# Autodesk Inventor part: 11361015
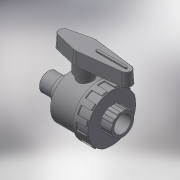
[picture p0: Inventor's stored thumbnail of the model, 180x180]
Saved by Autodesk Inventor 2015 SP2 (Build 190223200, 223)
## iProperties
Created: 2017-11
Part Number: 11361015
Material: Generic
Description: PLASSON ONE NUT VALVE MALE-FEMALE ADAPTOR 1.1/2" PVC
Document SubType Name: Modeling
Designer: KIM
Density: 1 g/cm^3
Appearance: Default
Author: KIM
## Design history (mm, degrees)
derived "113610.ipt"
feature "Solid1::113610.ipt"
tag "TaggingFeature1"
body "Solid1"
other parameters: "d2" = 96, "d4" = 35.876, "d8" = 86.4, "d13" = 1.34535, "d25" = 0.8969, "d26" = 1.34535, "d29" = 16.5, "d30" = 0, "d35" = 1.34535, "d39" = 48, "d45" = 360 deg, "d47" = 0.8969, "d50" = 52.8, "d51" = 28.8, "d53" = 0, "d58" = 0, "d59" = 1.34535, "d63" = 38.4, "d64" = 86, "d68" = 19.2, "d69" = 33, "d70" = 21.5, "d71" = 3 deg, "d73" = 1.92, "d74" = 44, "d75" = 2.58, "d76" = 0, "d77" = 0.8969, "d78" = 44.845, "d79" = 22, "d80" = 96, "d81" = 23.1, "d82" = 92.16, "d83" = 17.6, "d84" = 62.783, "d85" = 33.4621, "d87" = 120 deg, "d90" = 360 deg, "d92" = 14.4, "d95" = 7.2, "d96" = 47.803, "d97" = 26.4, "d98" = 22, "d99" = 15 deg, "d100" = 57.3636, "d101" = 8.969, "d102" = 4.4845, "G_" = 44.845, "l_" = 22, "K_" = 96, "F_" = 86, "R_" = 47.803, "d67" = 38.4, "d72" = 9.6
